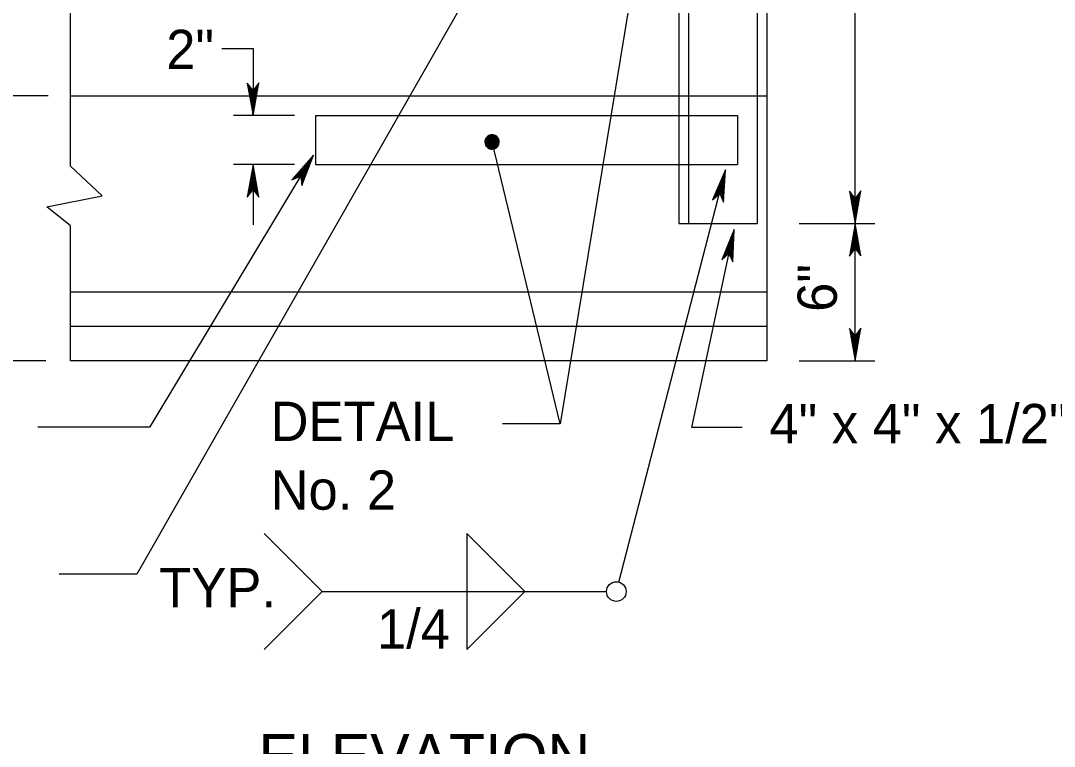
# Model space of a CAD drawing. Extents: x 499883 to 500983, y 499104 to 499764.
# Drawn here: x 500293.1 to 500398.4, y 499577.6 to 499651.5 of the extents above; entities that cross this region are included whole.
import ezdxf

# ---------------------------------------------------------------- set-up
doc = ezdxf.new("R2010")
doc.units = 0
doc.layers.add('24', color=7, linetype='Continuous')
doc.layers.add('5', color=7, linetype='Continuous')

msp = doc.modelspace()

# ---------------------------------------------------------------- linework, layer by layer
at = {"layer": '24'}
for points in [[(500347.64, 499669.95), (500304.96, 499595.14), (500297.04, 499595.14)], [(500355.63, 499656.25), (500348.09, 499610.47), (500342.22, 499610.47)], [(500316.79, 499641.86), (500317.38, 499645.18), (500316.79, 499644.39), (500316.21, 499645.16), (500316.79, 499641.86), (500316.78, 499642.08), (500317.34, 499645.09), (500316.78, 499644.32), (500316.26, 499645.03), (500316.77, 499642.2), (500316.79, 499642.31), (500317.25, 499644.89), (500316.78, 499644.31), (500316.33, 499644.9), (500316.79, 499642.36), (500316.77, 499642.47), (500317.18, 499644.72), (500316.79, 499644.28), (500316.39, 499644.73), (500316.77, 499642.79), (500316.77, 499642.98), (500317.1, 499644.55), (500316.8, 499644.25), (500316.47, 499644.58), (500316.79, 499643.01), (500316.8, 499643.19), (500317, 499644.37), (500316.77, 499644.15), (500316.55, 499644.39), (500316.79, 499643.35), (500316.81, 499643.52), (500316.94, 499644.23), (500316.78, 499644.11), (500316.61, 499644.31), (500316.79, 499643.6), (500316.9, 499644.07), (500316.77, 499644), (500316.65, 499644.21), (500316.77, 499643.72), (500316.85, 499644.03), (500316.75, 499643.9), (500316.69, 499644.05), (500316.78, 499643.9), (500316.8, 499643.98)], [(500348.09, 499610.47), (500341.14, 499639.17)], [(500322.94, 499637.82), (500320.75, 499635.31), (500321.65, 499635.68), (500321.75, 499634.73), (500322.94, 499637.82), (500322.83, 499637.63), (500320.84, 499635.36), (500321.69, 499635.73), (500321.78, 499634.87), (500322.78, 499637.52), (500322.71, 499637.44), (500321.01, 499635.49), (500321.7, 499635.74), (500321.78, 499635.01), (500322.68, 499637.39), (500322.64, 499637.29), (500321.15, 499635.6), (500321.71, 499635.77), (500321.82, 499635.18), (500322.48, 499637.02), (500322.38, 499636.86), (500321.31, 499635.69), (500321.72, 499635.8), (500321.83, 499635.36), (500322.35, 499636.84), (500322.25, 499636.7), (500321.48, 499635.8), (500321.79, 499635.87), (500321.86, 499635.55), (500322.18, 499636.55), (500322.08, 499636.42), (500321.6, 499635.89), (500321.8, 499635.91), (500321.85, 499635.65), (500322.05, 499636.34), (500321.72, 499636), (500321.86, 499636), (500321.87, 499635.76), (500322.01, 499636.23), (500321.79, 499636.01), (500321.94, 499636.07), (500321.91, 499635.92), (500321.91, 499636.09), (500321.85, 499636.03)], [(500316.79, 499636.86), (500316.2, 499633.54), (500316.79, 499634.33), (500317.37, 499633.55), (500316.79, 499636.86), (500316.8, 499636.64), (500316.25, 499633.63), (500316.8, 499634.39), (500317.32, 499633.69), (500316.81, 499636.52), (500316.79, 499636.41), (500316.33, 499633.83), (500316.8, 499634.41), (500317.25, 499633.81), (500316.79, 499636.36), (500316.81, 499636.25), (500316.4, 499633.99), (500316.79, 499634.43), (500317.2, 499633.99), (500316.81, 499635.93), (500316.81, 499635.74), (500316.48, 499634.16), (500316.78, 499634.47), (500317.11, 499634.14), (500316.79, 499635.71), (500316.78, 499635.53), (500316.58, 499634.34), (500316.81, 499634.57), (500317.04, 499634.32), (500316.79, 499635.37), (500316.77, 499635.2), (500316.64, 499634.49), (500316.8, 499634.6), (500316.98, 499634.41), (500316.79, 499635.11), (500316.68, 499634.65), (500316.81, 499634.71), (500316.93, 499634.51), (500316.81, 499634.99), (500316.73, 499634.69), (500316.83, 499634.82), (500316.89, 499634.67), (500316.8, 499634.82), (500316.78, 499634.74)], [(500364.91, 499636.33), (500363.59, 499633.28), (500364.34, 499633.91), (500364.72, 499633.03), (500364.91, 499636.33), (500364.86, 499636.12), (500363.66, 499633.36), (500364.36, 499633.97), (500364.7, 499633.17), (500364.85, 499636), (500364.81, 499635.9), (500363.78, 499633.53), (500364.36, 499633.98), (500364.66, 499633.31), (500364.79, 499635.85), (500364.78, 499635.74), (500363.89, 499633.67), (500364.36, 499634.01), (500364.65, 499633.49), (500364.71, 499635.44), (500364.67, 499635.26), (500364, 499633.82), (500364.36, 499634.04), (500364.6, 499633.65), (500364.65, 499635.23), (500364.6, 499635.06), (500364.13, 499633.97), (500364.41, 499634.13), (500364.57, 499633.85), (500364.57, 499634.9), (500364.52, 499634.74), (500364.22, 499634.09), (500364.4, 499634.17), (500364.53, 499633.94), (500364.51, 499634.66), (500364.3, 499634.24), (500364.44, 499634.27), (500364.51, 499634.05), (500364.5, 499634.54), (500364.36, 499634.27), (500364.49, 499634.37), (500364.51, 499634.21), (500364.45, 499634.37), (500364.42, 499634.3)], [(500364.91, 499636.33), (500363.59, 499633.28), (500364.34, 499633.91), (500364.72, 499633.03), (500364.91, 499636.33), (500364.86, 499636.12), (500363.66, 499633.36), (500364.36, 499633.97), (500364.7, 499633.17), (500364.85, 499636), (500364.81, 499635.9), (500363.78, 499633.53), (500364.36, 499633.98), (500364.66, 499633.31), (500364.79, 499635.85), (500364.78, 499635.74), (500363.89, 499633.67), (500364.36, 499634.01), (500364.65, 499633.49), (500364.71, 499635.44), (500364.67, 499635.26), (500364, 499633.82), (500364.36, 499634.04), (500364.6, 499633.65), (500364.65, 499635.23), (500364.6, 499635.06), (500364.13, 499633.97), (500364.41, 499634.13), (500364.57, 499633.85), (500364.57, 499634.9), (500364.52, 499634.74), (500364.22, 499634.09), (500364.4, 499634.17), (500364.53, 499633.94), (500364.51, 499634.66), (500364.3, 499634.24), (500364.44, 499634.27), (500364.51, 499634.05), (500364.5, 499634.54), (500364.36, 499634.27), (500364.49, 499634.37), (500364.51, 499634.21), (500364.45, 499634.37), (500364.42, 499634.3)], [(500365.79, 499630.24), (500364.54, 499627.16), (500365.27, 499627.81), (500365.67, 499626.94), (500365.79, 499630.24), (500365.75, 499630.03), (500364.6, 499627.24), (500365.29, 499627.87), (500365.65, 499627.08), (500365.73, 499629.91), (500365.7, 499629.81), (500364.72, 499627.42), (500365.29, 499627.88), (500365.6, 499627.22), (500365.69, 499629.76), (500365.68, 499629.65), (500364.82, 499627.56), (500365.29, 499627.91), (500365.59, 499627.39), (500365.61, 499629.34), (500365.57, 499629.16), (500364.94, 499627.71), (500365.29, 499627.94), (500365.54, 499627.56), (500365.55, 499629.13), (500365.51, 499628.96), (500365.07, 499627.86), (500365.33, 499628.04), (500365.5, 499627.75), (500365.48, 499628.81), (500365.43, 499628.65), (500365.15, 499627.99), (500365.33, 499628.07), (500365.46, 499627.85), (500365.43, 499628.56), (500365.23, 499628.14), (500365.36, 499628.17), (500365.44, 499627.95), (500365.42, 499628.44), (500365.28, 499628.17), (500365.41, 499628.27), (500365.44, 499628.11), (500365.38, 499628.27), (500365.34, 499628.2)]]:
    msp.add_lwpolyline(points, dxfattribs=at)
for radius, start, end in [(0.738, 283.6184, 103.6184), (0.738, 103.6184, 283.6184), (0.714, 103.6184, 283.6184), (0.689, 103.6184, 283.6184), (0.664, 103.6184, 283.6184), (0.64, 103.6184, 283.6184), (0.615, 103.6184, 283.6184), (0.591, 103.6184, 283.6184), (0.566, 103.6184, 283.6184), (0.541, 103.6184, 283.6184), (0.517, 103.6184, 283.6184), (0.492, 103.6184, 283.6184), (0.468, 103.6184, 283.6184), (0.443, 103.6184, 283.6184), (0.418, 103.6184, 283.6184), (0.394, 103.6184, 283.6184), (0.369, 103.6184, 283.6184), (0.344, 103.6184, 283.6184), (0.32, 103.6184, 283.6184), (0.295, 103.6184, 283.6184), (0.271, 103.6184, 283.6184), (0.246, 103.6184, 283.6184), (0.221, 103.6184, 283.6184), (0.197, 103.6184, 283.6184), (0.714, 283.6184, 103.6184), (0.172, 103.6184, 283.6184), (0.689, 283.6184, 103.6184), (0.664, 283.6184, 103.6184), (0.64, 283.6184, 103.6184), (0.148, 103.6184, 283.6184), (0.615, 283.6184, 103.6184), (0.591, 283.6184, 103.6184), (0.566, 283.6184, 103.6184), (0.541, 283.6184, 103.6184), (0.517, 283.6184, 103.6184), (0.492, 283.6184, 103.6184), (0.123, 103.6184, 283.6184), (0.468, 283.6184, 103.6184), (0.443, 283.6184, 103.6184), (0.418, 283.6184, 103.6184), (0.0984, 103.6184, 283.6184), (0.394, 283.6184, 103.6184), (0.369, 283.6184, 103.6184), (0.344, 283.6184, 103.6184), (0.32, 283.6184, 103.6184), (0.295, 283.6184, 103.6184), (0.0738, 103.6184, 283.6184), (0.271, 283.6184, 103.6184), (0.246, 283.6184, 103.6184), (0.221, 283.6184, 103.6184), (0.197, 283.6184, 103.6184), (0.0492, 103.6184, 283.6184), (0.172, 283.6184, 103.6184), (0.148, 283.6184, 103.6184), (0.123, 283.6184, 103.6184), (0.0984, 283.6184, 103.6184), (0.0738, 283.6184, 103.6184), (0.0246, 103.6184, 283.6184), (0.0492, 283.6184, 103.6184), (0.0246, 283.6184, 103.6184)]:
    msp.add_arc((500341.14, 499639.17), radius, start, end, dxfattribs=at)
at = {"layer": '5'}
for p, q in [((500360.15, 499681.83), (500360.15, 499630.86)), ((500361.14, 499681.83), (500361.14, 499630.86)), ((500368.14, 499681.83), (500368.14, 499630.86)), ((500369.14, 499681.83), (500369.14, 499616.88)), ((500378.13, 499630.86), (500378.13, 499681.83)), ((500298.19, 499636.71), (500298.19, 499661)), ((500295.93, 499643.85), (500284.28, 499643.85)), ((500298.19, 499643.85), (500369.14, 499643.85)), ((500321.03, 499641.86), (500314.79, 499641.86)), ((500323.17, 499641.86), (500366.14, 499641.86)), ((500323.17, 499641.86), (500323.17, 499636.86)), ((500366.14, 499641.86), (500366.14, 499636.86)), ((500321.03, 499636.86), (500314.79, 499636.86)), ((500316.79, 499636.86), (500316.79, 499630.71)), ((500323.17, 499636.86), (500366.14, 499636.86)), ((500298.19, 499636.71), (500301.41, 499633.67)), ((500354.05, 499594.34), (500364.91, 499636.33)), ((500295.8, 499632.57), (500301.41, 499633.67)), ((500298.19, 499630.62), (500295.8, 499632.57)), ((500298.19, 499616.88), (500298.19, 499630.62)), ((500360.15, 499630.86), (500368.14, 499630.86)), ((500372.44, 499630.86), (500380.13, 499630.86)), ((500378.13, 499616.88), (500378.13, 499630.86)), ((500369.14, 499623.87), (500298.19, 499623.87)), ((500369.14, 499620.37), (500298.19, 499620.37)), ((500295.68, 499616.88), (500284.28, 499616.88)), ((500369.14, 499616.88), (500298.19, 499616.88)), ((500372.44, 499616.88), (500380.13, 499616.88)), ((500317.93, 499599.27), (500323.82, 499593.37)), ((500338.58, 499599.27), (500344.47, 499593.37)), ((500338.58, 499599.27), (500338.58, 499587.48)), ((500323.82, 499593.37), (500317.93, 499587.48)), ((500323.82, 499593.37), (500344.47, 499593.37)), ((500344.47, 499593.37), (500338.58, 499587.48)), ((500344.47, 499593.37), (500352.8, 499593.37))]:
    msp.add_line(p, q, dxfattribs=at)
for points in [[(500313.61, 499648.69), (500316.79, 499648.69), (500316.79, 499641.86)], [(500294.86, 499610.16), (500306.31, 499610.16), (500322.94, 499637.82)], [(500378.13, 499630.86), (500378.72, 499634.19), (500378.13, 499633.39), (500377.55, 499634.17), (500378.13, 499630.86), (500378.13, 499631.09), (500378.68, 499634.1), (500378.12, 499633.33), (500377.6, 499634.04), (500378.12, 499631.2), (500378.13, 499631.32), (500378.59, 499633.89), (500378.12, 499633.32), (500377.67, 499633.91), (500378.13, 499631.37), (500378.12, 499631.48), (500378.52, 499633.73), (500378.13, 499633.29), (500377.73, 499633.74), (500378.11, 499631.8), (500378.11, 499631.98), (500378.44, 499633.56), (500378.14, 499633.26), (500377.81, 499633.59), (500378.13, 499632.02), (500378.14, 499632.2), (500378.35, 499633.38), (500378.11, 499633.15), (500377.89, 499633.4), (500378.13, 499632.36), (500378.15, 499632.53), (500378.28, 499633.24), (500378.12, 499633.12), (500377.95, 499633.32), (500378.13, 499632.61), (500378.24, 499633.08), (500378.11, 499633.01), (500377.99, 499633.21), (500378.11, 499632.73), (500378.19, 499633.03), (500378.09, 499632.91), (500378.03, 499633.05), (500378.12, 499632.91), (500378.14, 499632.98)], [(500378.13, 499630.86), (500377.54, 499627.54), (500378.13, 499628.33), (500378.71, 499627.56), (500378.13, 499630.86), (500378.14, 499630.64), (500377.59, 499627.63), (500378.14, 499628.4), (500378.66, 499627.69), (500378.15, 499630.52), (500378.13, 499630.41), (500377.67, 499627.84), (500378.14, 499628.41), (500378.59, 499627.82), (500378.13, 499630.36), (500378.15, 499630.25), (500377.74, 499628), (500378.13, 499628.44), (500378.54, 499627.99), (500378.15, 499629.93), (500378.15, 499629.74), (500377.83, 499628.17), (500378.12, 499628.47), (500378.45, 499628.14), (500378.13, 499629.71), (500378.12, 499629.53), (500377.92, 499628.35), (500378.15, 499628.57), (500378.38, 499628.33), (500378.13, 499629.37), (500378.11, 499629.2), (500377.98, 499628.49), (500378.14, 499628.61), (500378.32, 499628.41), (500378.13, 499629.12), (500378.02, 499628.65), (500378.15, 499628.72), (500378.28, 499628.51), (500378.15, 499629), (500378.07, 499628.69), (500378.17, 499628.82), (500378.23, 499628.68), (500378.14, 499628.82), (500378.12, 499628.74)], [(500366.61, 499610.08), (500361.48, 499610.08), (500365.79, 499630.24)], [(500378.13, 499616.88), (500378.72, 499620.2), (500378.13, 499619.41), (500377.55, 499620.18), (500378.13, 499616.88), (500378.13, 499617.1), (500378.68, 499620.11), (500378.12, 499619.34), (500377.6, 499620.05), (500378.12, 499617.22), (500378.13, 499617.33), (500378.59, 499619.9), (500378.12, 499619.33), (500377.67, 499619.92), (500378.13, 499617.38), (500378.12, 499617.49), (500378.52, 499619.74), (500378.13, 499619.3), (500377.73, 499619.75), (500378.11, 499617.81), (500378.11, 499618), (500378.44, 499619.57), (500378.14, 499619.27), (500377.81, 499619.6), (500378.13, 499618.03), (500378.14, 499618.21), (500378.35, 499619.39), (500378.11, 499619.16), (500377.89, 499619.41), (500378.13, 499618.37), (500378.15, 499618.54), (500378.28, 499619.25), (500378.12, 499619.13), (500377.95, 499619.33), (500378.13, 499618.62), (500378.24, 499619.09), (500378.11, 499619.02), (500377.99, 499619.23), (500378.11, 499618.74), (500378.19, 499619.05), (500378.09, 499618.92), (500378.03, 499619.06), (500378.12, 499618.92), (500378.14, 499618.99)]]:
    msp.add_lwpolyline(points, dxfattribs=at)
msp.add_circle((500353.8, 499593.37), 0.999, dxfattribs=at)

# ---------------------------------------------------------------- texts
for s, height, p in [('2"', 4, (500307.95, 499646.59)), ('DETAIL', 4, (500318.58, 499608.71)), ('4" x 4" x 1/2" TUBE', 4, (500369.39, 499608.48)), ('No. 2', 4, (500318.58, 499601.71)), ('TYP.', 4, (500307.24, 499591.76)), ('1/4', 4, (500329.41, 499587.57)), ('ELEVATION', 4.5, (500317.36, 499574.36))]:
    msp.add_text(s, height=height, dxfattribs=at).set_placement(p)
msp.add_text('6"', height=4, rotation=90, dxfattribs=at).set_placement((500376.26, 499621.86))

doc.saveas('drawing.dxf')
